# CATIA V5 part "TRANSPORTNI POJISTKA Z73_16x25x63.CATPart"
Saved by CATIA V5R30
Part number: TRANSPORTNI POJISTKA Z73/16x25x63
Bounding box of the stored display mesh (mm): x -13 to 50, y -12.5 to 12.5, z -11.2 to 16.1
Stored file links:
  C:\Users\ondra\Desktop\PŘÍLOHA P III\CATIA\TRANSPORTNI POJISTKA Z73_16x25x63.CATPart
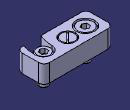
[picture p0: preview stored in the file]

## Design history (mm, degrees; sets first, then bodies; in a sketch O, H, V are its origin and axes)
Set1
  DatumSurface1 to DatumSurface28 "Z73/16x2"
  DatumSurface29 to DatumSurface64 "Z381/8x1"
  DatumSurface65 to DatumSurface92 "Z36/8x16"
  DatumSurface93 to DatumSurface121 "Z31/8x18"
  Join1: Elements (DatumSurface1; DatumSurface2; DatumSurface3; DatumSurface4; DatumSurface5; DatumSurface6; DatumSurface7; DatumSurface8; DatumSurface9; DatumSurface10; DatumSurface11; DatumSurface12; DatumSurface13; DatumSurface14; DatumSurface15; DatumSurface16; DatumSurface17; DatumSurface18; DatumSurface19; DatumSurface20; DatumSurface21; DatumSurface22; DatumSurface23; DatumSurface24; DatumSurface25; DatumSurface26; DatumSurface27; DatumSurface28)
  Join2: Elements (DatumSurface29; DatumSurface30; DatumSurface31; DatumSurface32; DatumSurface33; DatumSurface34; DatumSurface35; DatumSurface36; DatumSurface37; DatumSurface38; DatumSurface39; DatumSurface40; DatumSurface41; DatumSurface42; DatumSurface43; DatumSurface44; DatumSurface45; DatumSurface46; DatumSurface47; DatumSurface48; DatumSurface49; DatumSurface50; DatumSurface51; DatumSurface52; DatumSurface53; DatumSurface54; DatumSurface55; DatumSurface56; DatumSurface57; DatumSurface58; DatumSurface59; DatumSurface60; DatumSurface61; DatumSurface62; DatumSurface63; DatumSurface64)
  Join3: Elements (DatumSurface65; DatumSurface66; DatumSurface67; DatumSurface68; DatumSurface69; DatumSurface70; DatumSurface71; DatumSurface72; DatumSurface73; DatumSurface74; DatumSurface75; DatumSurface76; DatumSurface77; DatumSurface78; DatumSurface79; DatumSurface80; DatumSurface81; DatumSurface82; DatumSurface83; DatumSurface84; DatumSurface85; DatumSurface86; DatumSurface87; DatumSurface88; DatumSurface89; DatumSurface90; DatumSurface91; DatumSurface92)
  Join4: Elements (DatumSurface93; DatumSurface94; DatumSurface95; DatumSurface96; DatumSurface97; DatumSurface98; DatumSurface99; DatumSurface100; DatumSurface101; DatumSurface102; DatumSurface103; DatumSurface104; DatumSurface105; DatumSurface106; DatumSurface107; DatumSurface108; DatumSurface109; DatumSurface110; DatumSurface111; DatumSurface112; DatumSurface113; DatumSurface114; DatumSurface115; DatumSurface116; DatumSurface117; DatumSurface118; DatumSurface119; DatumSurface120; DatumSurface121)
Set2 "Geometry Failure"
  Set3 "FaceKO#Z31/8x18#3117"
    DatumSurface122 "Sur3117_1"
    Circle1 "Crv3117_1": stored without definition
    DatumCurve1 "PCrv3117_1"
    Circle2 "Crv3117_2": stored without definition
    DatumCurve2 "PCrv3117_2"
    Circle3 "Crv3117_3": stored without definition
    DatumCurve3 "PCrv3117_3"
    Circle4 "Crv3117_4": stored without definition
    DatumCurve4 "PCrv3117_4"
Body1 (main body)
  CloseSurface1: CloseElement Join1
  CloseSurface2: CloseElement Join2
  CloseSurface3: CloseElement Join3
  CloseSurface4: CloseElement Join4
  Plane1: type Offset, RefPlane yz-plane, Offset 13, reversed
  Plane2: type Offset, RefPlane yz-plane, Offset 50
